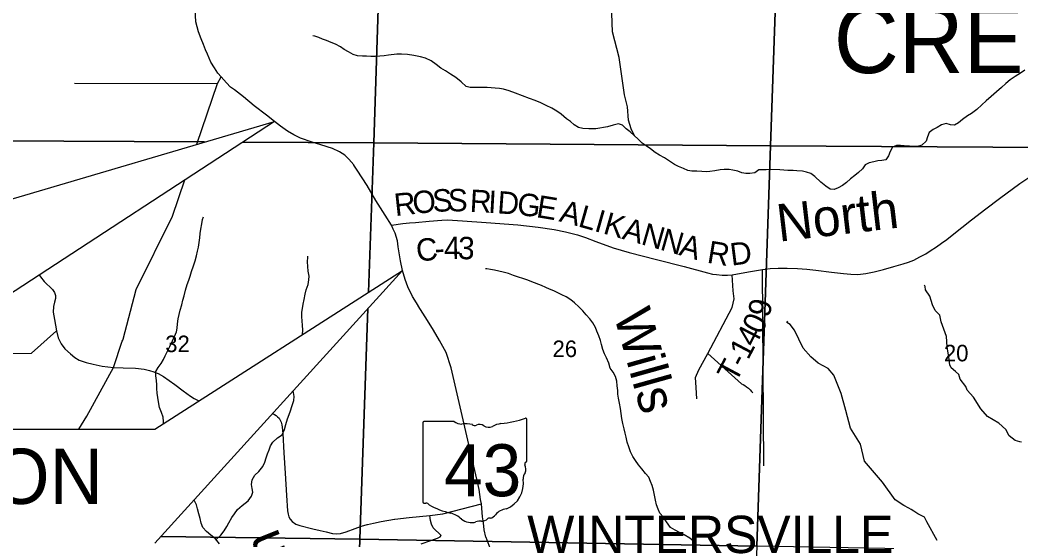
# Model space of a CAD drawing. Extents: x -19 to 40.8, y -1.8 to 26.1.
# Drawn here: x 4.466 to 7.005, y 16.956 to 18.273 of the extents above; entities that cross this region are included whole.
import ezdxf

# ---------------------------------------------------------------- set-up
doc = ezdxf.new("R2010")
doc.units = 0
for name, color, linetype in [('GM_X_Corporation', 7, 'Continuous'), ('GM_X_County_Road_Text', 7, 'Continuous'), ('GM_X_Major_River_Text', 7, 'Continuous'), ('GM_X_Minor_River', 7, 'Continuous'), ('GM_X_Rail_Line', 7, 'Continuous'), ('GM_X_Section', 7, 'Continuous'), ('GM_X_Section_Text', 7, 'Continuous'), ('GM_X_State_Location', 7, 'Continuous'), ('GM_X_State_Route', 7, 'Continuous'), ('GM_X_Township_Road_Text', 7, 'Continuous'), ('GM_X_Township_Text', 7, 'Continuous'), ('GM_X_Unincorporated_Text', 7, 'Continuous'), ('RW_P_Text', 7, 'Continuous'), ('SH_Text', 7, 'Continuous')]:
    doc.layers.add(name, color=color, linetype=linetype)

msp = doc.modelspace()

# ---------------------------------------------------------------- linework, layer by layer
at = {"layer": 'GM_X_Corporation'}
for points in [[(5.4077, 17.7534), (5.4363, 17.7577), (5.4536, 17.7598), (5.469, 17.7606), (5.5039, 17.7635), (5.5357, 17.766), (5.5498, 17.7669), (5.588, 17.7648), (5.6479, 17.76), (5.7282, 17.7541), (5.7803, 17.7488), (5.8207, 17.7427), (5.8495, 17.7367), (5.8797, 17.7287), (5.8999, 17.722), (5.9264, 17.7118), (5.9705, 17.696), (6.0105, 17.6847), (6.0805, 17.6669), (6.1507, 17.6486), (6.2097, 17.6327), (6.2223, 17.6298), (6.2326, 17.6284), (6.2468, 17.627), (6.2606, 17.6265), (6.2721, 17.6278), (6.3134, 17.6356), (6.3494, 17.6416), (6.3689, 17.6436), (6.3892, 17.6444), (6.4115, 17.6445), (6.4383, 17.6439), (6.4619, 17.642), (6.4842, 17.6394), (6.5242, 17.6341), (6.5547, 17.6307), (6.5734, 17.6291), (6.5908, 17.6288), (6.6109, 17.6309), (6.6324, 17.6354), (6.6558, 17.6411), (6.6826, 17.6486), (6.7063, 17.6554), (6.7198, 17.6598), (6.7329, 17.6652), (6.7485, 17.6729), (6.7635, 17.6813), (6.7748, 17.6883), (6.7906, 17.6986), (6.8032, 17.7077), (6.8169, 17.7176), (6.8304, 17.7285), (6.8791, 17.767), (6.9155, 17.7949), (6.9507, 17.8215), (7.002, 17.8591), (7.0427, 17.8858)], [(5.5195, 16.9585), (5.525, 16.9603), (5.5316, 16.9634), (5.5342, 16.9671), (5.5137, 16.9866), (5.5092, 16.9958), (5.5067, 17.0054), (5.5052, 17.0174)], [(5.483, 16.9459), (5.5075, 16.9546), (5.5195, 16.9585)]]:
    msp.add_lwpolyline(points, dxfattribs=at)
at = {"layer": 'GM_X_Rail_Line'}
for points in [[(5.3125, 17.9058), (5.312, 17.9066), (5.2998, 17.921), (5.2894, 17.9307), (5.2757, 17.9394), (5.2586, 17.9477), (5.2285, 17.9575), (5.2069, 17.9639), (5.1769, 17.9744), (5.1605, 17.9825), (5.1443, 17.9922), (5.1266, 18.0046), (5.1108, 18.0166), (5.0907, 18.0322), (5.0594, 18.0564), (5.0326, 18.0785), (5.0093, 18.0968), (4.9999, 18.1037), (4.9891, 18.1139), (4.9755, 18.1295), (4.9674, 18.1388), (4.9589, 18.1522), (4.95, 18.1671), (4.9408, 18.1872), (4.9365, 18.1979), (4.9309, 18.2115), (4.9248, 18.226), (4.9181, 18.2436), (4.9146, 18.2562), (4.9116, 18.2692), (4.9099, 18.3009)], [(5.4754, 17.5499), (5.4613, 17.5724), (5.4496, 17.597), (5.4424, 17.6161), (5.4357, 17.6388), (5.4305, 17.6634), (5.4252, 17.6987), (5.4229, 17.7135), (5.4172, 17.7334), (5.4121, 17.7435), (5.4077, 17.7534), (5.3918, 17.7785), (5.3686, 17.8164), (5.3459, 17.854), (5.3211, 17.8926), (5.3125, 17.9058)], [(4.5141, 17.6275), (4.5179, 17.6223), (4.5271, 17.6104), (4.5481, 17.5902), (4.5529, 17.5825), (4.5552, 17.5757), (4.5557, 17.5677), (4.5534, 17.5588), (4.5501, 17.5475), (4.5494, 17.5333), (4.5534, 17.5144), (4.558, 17.4856), (4.5623, 17.4681), (4.5699, 17.4532), (4.5795, 17.4403), (4.5934, 17.4274), (4.6047, 17.4181), (4.6153, 17.4115), (4.6335, 17.4058), (4.6514, 17.4009), (4.6739, 17.3966), (4.7027, 17.3929), (4.7269, 17.3922), (4.7581, 17.3909), (4.7805, 17.3886), (4.7939, 17.3855), (4.8051, 17.382), (4.811, 17.3796)], [(5.636, 17.0471), (5.634, 17.0581), (5.6305, 17.0839), (5.6245, 17.1099), (5.5594, 17.3923), (5.5464, 17.4309), (5.5299, 17.461), (5.5149, 17.4875), (5.4992, 17.5121), (5.476, 17.5491), (5.4754, 17.5499)], [(4.811, 17.3796), (4.816, 17.3776), (4.8299, 17.3699), (4.8442, 17.36), (4.858, 17.3496), (4.8794, 17.3339), (4.8979, 17.3204), (4.9075, 17.3139), (4.9178, 17.3094), (4.92, 17.3087)], [(5.1061, 17.2762), (5.111, 17.2737), (5.1155, 17.2708), (5.119, 17.268), (5.1226, 17.2642), (5.1259, 17.2596), (5.128, 17.2546), (5.13, 17.2479), (5.1308, 17.2416), (5.1319, 17.2259), (5.1345, 17.1762), (5.1378, 17.1248), (5.1415, 17.0681), (5.1438, 17.0295), (5.1456, 17.0214), (5.1476, 17.0147), (5.1508, 17.0082), (5.1557, 17.0023), (5.1655, 16.9959), (5.1755, 16.992), (5.208, 16.984), (5.2273, 16.9796), (5.2422, 16.9761), (5.2583, 16.9717), (5.2677, 16.9715), (5.2787, 16.9723), (5.293, 16.9761), (5.3158, 16.9851), (5.3315, 16.9906), (5.3464, 16.9948), (5.3474, 16.9951)], [(5.4155, 17.0085), (5.4165, 17.0087), (5.4528, 17.0125), (5.5052, 17.0174), (5.5383, 17.0218), (5.636, 17.0471)], [(5.6478, 16.9623), (5.6474, 16.9632), (5.6431, 16.9811), (5.6411, 16.9989), (5.6392, 17.0147), (5.636, 17.0471)], [(5.3474, 16.9951), (5.3627, 16.9985), (5.3814, 17.0022), (5.4155, 17.0085)], [(5.7631, 16.7982), (5.7251, 16.8529), (5.6987, 16.8841), (5.6791, 16.903), (5.6671, 16.918), (5.6582, 16.9352), (5.6478, 16.9623)]]:
    msp.add_lwpolyline(points, dxfattribs=at)
at = {"layer": 'GM_X_Section'}
for points in [[(6.0242, 17.98), (6.0157, 17.998), (6.0089, 18.0195), (6.0068, 18.0533), (5.9994, 18.084), (5.9853, 18.1788), (5.969, 18.2435), (5.967, 18.2899), (5.9628, 18.3157), (5.9531, 18.3752), (5.9494, 18.3915), (5.9466, 18.3975), (5.9447, 18.4016), (5.946, 18.4104)], [(5.8933, 17.9985), (5.8826, 18.0012), (5.8717, 18.0081), (5.862, 18.0162), (5.8523, 18.0234), (5.8382, 18.0348), (5.8273, 18.0428), (5.8145, 18.05), (5.8006, 18.0572), (5.7864, 18.064), (5.7725, 18.0692), (5.7583, 18.0749), (5.7406, 18.0815), (5.7225, 18.0878), (5.7063, 18.0941), (5.6921, 18.0983), (5.6822, 18.1002), (5.6711, 18.101), (5.6605, 18.1014), (5.6506, 18.1023), (5.6392, 18.1023), (5.627, 18.1027), (5.6072, 18.1021), (5.5976, 18.1052), (5.5847, 18.1169), (5.5714, 18.1275), (5.5579, 18.1362), (5.5447, 18.1446), (5.5327, 18.1518), (5.5217, 18.161), (5.5085, 18.1701), (5.4946, 18.1765), (5.4812, 18.1806), (5.4647, 18.1839), (5.4483, 18.186), (5.4335, 18.1871), (5.4213, 18.1871), (5.4001, 18.1841), (5.3891, 18.1827), (5.3785, 18.1816), (5.3664, 18.1812), (5.3557, 18.1812), (5.3443, 18.1816), (5.3344, 18.1817), (5.3215, 18.1824), (5.3103, 18.1863), (5.2987, 18.1927), (5.2882, 18.1992), (5.2785, 18.2058), (5.2658, 18.2126), (5.255, 18.2165), (5.2427, 18.2214), (5.2331, 18.2253), (5.2234, 18.2288), (5.2134, 18.2323), (5.2081, 18.2336)], [(7.0149, 18.1463), (7.0033, 18.1388), (6.9903, 18.13)], [(6.9903, 18.13), (6.9772, 18.1216), (6.9661, 18.1129), (6.9554, 18.1026), (6.9424, 18.0916), (6.9295, 18.0798), (6.9165, 18.0687), (6.9058, 18.0585), (6.8929, 18.0471), (6.8791, 18.0367), (6.8691, 18.0303), (6.8564, 18.0216), (6.8464, 18.0133), (6.836, 18.0072), (6.8257, 18.0077), (6.8149, 18.0111), (6.8036, 18.0078), (6.7924, 18.0009), (6.782, 17.9957), (6.7723, 17.9885), (6.7677, 17.9773), (6.7642, 17.9662), (6.7531, 17.9567), (6.7422, 17.953), (6.7327, 17.9527), (6.7217, 17.9535), (6.7087, 17.9546), (6.6992, 17.9554), (6.6889, 17.9559), (6.6788, 17.9514), (6.673, 17.9405), (6.6685, 17.9294), (6.6619, 17.9193), (6.6521, 17.9174), (6.6419, 17.9163), (6.6313, 17.9141), (6.6196, 17.9115), (6.6099, 17.9062), (6.6026, 17.8965), (6.593, 17.8871), (6.5833, 17.8795), (6.5726, 17.8712), (6.5622, 17.8617), (6.5518, 17.8538), (6.541, 17.8482), (6.5308, 17.8437), (6.5209, 17.8452), (6.51, 17.8525), (6.4972, 17.8627), (6.4823, 17.8771), (6.4714, 17.8844), (6.461, 17.8882), (6.4503, 17.8906), (6.4366, 17.8909), (6.4271, 17.8917), (6.4134, 17.8924), (6.4034, 17.8933), (6.3935, 17.8937), (6.3684, 17.8944), (6.3586, 17.8941), (6.349, 17.8942), (6.3396, 17.8935), (6.3295, 17.8864), (6.3174, 17.8848), (6.3072, 17.8841), (6.2968, 17.8861), (6.2864, 17.8903), (6.2742, 17.893), (6.2642, 17.8946), (6.2521, 17.8946), (6.2415, 17.8935), (6.2282, 17.8912), (6.2157, 17.8893), (6.2059, 17.8889), (6.1956, 17.8894), (6.1823, 17.8901), (6.1701, 17.8905), (6.1598, 17.8921), (6.1486, 17.8974), (6.1363, 17.9023), (6.1262, 17.9077), (6.1157, 17.9142), (6.1006, 17.924), (6.0878, 17.9312), (6.0766, 17.9381), (6.0653, 17.9469), (6.0544, 17.9545), (6.0439, 17.9618), (6.0337, 17.9714), (6.0235, 17.9805), (6.0134, 17.9901), (6.0029, 17.9978), (5.9942, 18.0074), (5.9842, 18.0101), (5.9703, 18.0066), (5.9559, 18.0031), (5.9461, 18.0009), (5.9363, 17.9991), (5.9264, 17.998), (5.9086, 17.9975), (5.8933, 17.9985)], [(4.9059, 17.6503), (4.91, 17.6634), (4.9134, 17.676), (4.9161, 17.6879), (4.9181, 17.6982), (4.92, 17.7097), (4.9215, 17.7211), (4.9227, 17.7322), (4.9242, 17.7437), (4.9265, 17.757), (4.9288, 17.7681), (4.9313, 17.7743)], [(5.1821, 17.4765), (5.1828, 17.4872), (5.1824, 17.5001), (5.1814, 17.5099), (5.1806, 17.5224), (5.1807, 17.532), (5.1838, 17.5533), (5.1861, 17.5656), (5.1887, 17.5786), (5.1918, 17.5897), (5.1963, 17.6035), (5.1986, 17.615), (5.1987, 17.6245), (5.1968, 17.6366), (5.1956, 17.6492), (5.1949, 17.6609), (5.1953, 17.6723), (5.1956, 17.6746)], [(4.8295, 17.2507), (4.8297, 17.2563), (4.8286, 17.2669), (4.8244, 17.2789), (4.8191, 17.2917), (4.8167, 17.3057), (4.8152, 17.3167), (4.8137, 17.328), (4.813, 17.3398), (4.8123, 17.3493), (4.8116, 17.3599), (4.8105, 17.3713), (4.8101, 17.383), (4.8163, 17.3931), (4.8235, 17.4028), (4.8297, 17.4129), (4.834, 17.4226), (4.8397, 17.4342), (4.8454, 17.4461), (4.8521, 17.4608), (4.8575, 17.4716), (4.8628, 17.4832), (4.8641, 17.4927), (4.8653, 17.5034), (4.8671, 17.516), (4.8694, 17.5275), (4.8721, 17.5382), (4.8759, 17.5516), (4.879, 17.5635), (4.8816, 17.5746), (4.8854, 17.5888), (4.8895, 17.603), (4.8937, 17.6138), (4.8976, 17.6242), (4.901, 17.6365), (4.9059, 17.6503)], [(5.9444, 17.4385), (5.9409, 17.4509), (5.9379, 17.4615), (5.9342, 17.4732), (5.9292, 17.4848), (5.9251, 17.4945), (5.9191, 17.5058), (5.9111, 17.5158), (5.9021, 17.5261), (5.893, 17.5365), (5.8832, 17.5468), (5.8726, 17.5568), (5.8625, 17.5644), (5.8508, 17.5717), (5.84, 17.577), (5.8296, 17.5824), (5.8199, 17.5874), (5.8092, 17.5917), (5.7995, 17.5955), (5.7883, 17.6005), (5.7637, 17.6096), (5.7537, 17.6139), (5.741, 17.6184), (5.7299, 17.6219), (5.7176, 17.6264), (5.7045, 17.6309), (5.6911, 17.6347), (5.6804, 17.6374), (5.6689, 17.6393), (5.6593, 17.6413), (5.6494, 17.6425), (5.6463, 17.6428)], [(7.0059, 17.2034), (7.0017, 17.2041), (6.9899, 17.2077), (6.9746, 17.22), (6.9668, 17.2355), (6.9483, 17.2519), (6.9201, 17.2689), (6.9031, 17.2884), (6.8848, 17.3173), (6.8686, 17.3353), (6.8654, 17.3444), (6.8503, 17.3635), (6.8471, 17.3752), (6.8386, 17.3831), (6.8275, 17.392), (6.8244, 17.3996), (6.8217, 17.4189), (6.8179, 17.4454), (6.8159, 17.4716), (6.8028, 17.5083), (6.7991, 17.5253), (6.7871, 17.5377), (6.7808, 17.5516), (6.7733, 17.5735), (6.7631, 17.5901), (6.7615, 17.598), (6.7599, 17.6014)], [(6.7919, 16.954), (6.7661, 17.0014), (6.7602, 17.0139), (6.743, 17.0223), (6.7334, 17.029), (6.7262, 17.0331), (6.7201, 17.036), (6.7075, 17.0427), (6.6857, 17.0571), (6.6535, 17.1022), (6.6079, 17.1558), (6.5977, 17.1982), (6.5721, 17.2388), (6.5603, 17.2838), (6.5489, 17.3273), (6.53, 17.3734), (6.5157, 17.3899), (6.4901, 17.4035), (6.4721, 17.4199), (6.4524, 17.442), (6.4304, 17.4876), (6.4196, 17.5015), (6.4108, 17.5067), (6.4137, 17.5105)], [(6.1748, 16.9522), (6.1647, 16.9607), (6.1504, 16.969), (6.1384, 16.975), (6.1272, 16.9804), (6.1156, 16.9873), (6.1052, 17.0018), (6.098, 17.0133), (6.0886, 17.024), (6.0841, 17.0338), (6.0803, 17.0451), (6.0776, 17.0568), (6.0754, 17.0693), (6.073, 17.0821), (6.0689, 17.0934), (6.0647, 17.1043), (6.0606, 17.1148), (6.0523, 17.1244), (6.0428, 17.1363), (6.0349, 17.1463), (6.027, 17.1575), (6.0202, 17.1675), (6.0141, 17.1791), (6.0099, 17.1919), (6.0061, 17.204), (6.0031, 17.2164), (6.0005, 17.2266), (5.9978, 17.2375), (5.9947, 17.2511), (5.9921, 17.2636), (5.9902, 17.2761), (5.9886, 17.2886), (5.9863, 17.3026), (5.984, 17.315), (5.9825, 17.3253), (5.9818, 17.3347), (5.9807, 17.3465), (5.9792, 17.3582), (5.9765, 17.3703), (5.9705, 17.3812), (5.963, 17.3912), (5.9595, 17.4036), (5.953, 17.4171), (5.9481, 17.4276), (5.9444, 17.4385)], [(4.9629, 16.9565), (4.9752, 16.9677), (4.9836, 16.9786), (4.9901, 16.9895), (4.9955, 16.9991), (5.0031, 17.0123), (5.0093, 17.022), (5.0173, 17.0333), (5.0287, 17.0435), (5.044, 17.055), (5.0531, 17.0664), (5.0558, 17.0767), (5.0548, 17.0862), (5.0529, 17.0964), (5.0548, 17.1082), (5.0613, 17.1198), (5.0713, 17.1293), (5.0815, 17.1422), (5.0865, 17.153), (5.09, 17.1637), (5.0931, 17.1741), (5.0973, 17.1845), (5.1012, 17.1941), (5.1066, 17.2038), (5.1188, 17.2144), (5.1307, 17.222), (5.1364, 17.2355), (5.1398, 17.2482), (5.1443, 17.2631), (5.1505, 17.2808), (5.1561, 17.2966), (5.1599, 17.3096), (5.1611, 17.3196), (5.1597, 17.3298), (5.1584, 17.3337)], [(4.9717, 16.9463), (4.9615, 16.9582), (4.9497, 16.9681), (4.9384, 16.9772), (4.929, 16.9875), (4.9252, 16.9985), (4.9226, 17.0102), (4.9195, 17.0222), (4.9161, 17.0343), (4.9131, 17.0445), (4.9083, 17.0546), (4.9057, 17.0558)]]:
    msp.add_lwpolyline(points, dxfattribs=at)
at = {"layer": 'GM_X_State_Route'}
for p, q in [((4.6035, 18.1133), (4.9667, 18.1125)), ((6.3523, 17.1436), (6.3494, 17.6416))]:
    msp.add_line(p, q, dxfattribs=at)
for points in [[(4.9145, 17.9588), (4.9667, 18.1125), (4.9755, 18.1295)], [(4.7269, 17.4646), (4.7605, 17.5908), (4.8526, 17.7764), (4.8839, 17.8686)], [(6.1828, 17.3138), (6.1805, 17.3419), (6.1789, 17.3676), (6.1875, 17.3871), (6.2101, 17.4284), (6.2724, 17.5453), (6.2771, 17.5671), (6.2748, 17.5874), (6.2721, 17.6278)], [(4.4107, 17.4287), (4.4946, 17.4289), (4.558, 17.4856)], [(4.7027, 17.3929), (4.7251, 17.4592), (4.7262, 17.4618), (4.7269, 17.4646)], [(6.2101, 17.4284), (6.2958, 17.3517), (6.2998, 17.3496), (6.3044, 17.3468), (6.3088, 17.3437), (6.3133, 17.3401), (6.3176, 17.3361), (6.3211, 17.3324), (6.3246, 17.3283)], [(4.6145, 17.2367), (4.6349, 17.2694), (4.7027, 17.3929)]]:
    msp.add_lwpolyline(points, dxfattribs=at)
at = {"layer": 'GM_X_Unincorporated_Text'}
for p, q in [((5.4874, 17.2525), (5.4874, 17.0523)), ((5.5672, 17.2559), (5.49, 17.2559)), ((5.7511, 17.1562), (5.7511, 17.2609)), ((5.7511, 17.1562), (5.7511, 17.1562))]:
    msp.add_line(p, q, dxfattribs=at)
for centre, radius, start, end in [((5.4905, 17.2529), 0.00305, 98.1301, 188.1301), ((5.5856, 17.2791), 0.0296, 231.6195, 271.1119), ((5.5955, 17.1436), 0.1064, 80.4867, 94.9883), ((5.6196, 17.2539), 0.00855, 219.7921, 297.1024), ((5.6322, 17.2308), 0.0178, 54.4667, 119.1411), ((5.6551, 17.2625), 0.0214, 233.8562, 294.8282), ((5.6928, 17.1948), 0.0563, 97.3462, 120.7689), ((5.6572, 17.5287), 0.2796, 275.8445, 288.9065), ((5.7482, 17.2613), 0.00294, 351.8621, 97.738), ((5.7504, 17.1485), 0.00454, 107.944, 210.337), ((5.7215, 17.1353), 0.0273, 340.033, 23.6496), ((5.748, 17.1558), 0.00314, 289.6038, 7.7341), ((5.7616, 17.1124), 0.0198, 136.8065, 186.9296), ((5.6728, 17.0991), 0.0699, 292.3089, 8.9858), ((5.4905, 17.0519), 0.00308, 171.9584, 258.3066), ((5.491, 17.0724), 0.0235, 267.339, 280.6039), ((5.4958, 17.0408), 0.00848, 29.7484, 93.2717), ((5.6028, 17.2206), 0.2019, 240.4129, 257.1985), ((5.5426, 16.9624), 0.0632, 47.1842, 75.836), ((5.6538, 17.033), 0.0226, 282.8732, 323.2771), ((5.7023, 16.9962), 0.0383, 94.4031, 142.5768), ((5.611, 17.0398), 0.0401, 230.7004, 286.2918), ((5.6341, 16.9706), 0.0329, 85.6951, 111.2099), ((5.637, 17.0248), 0.0214, 268.777, 315.5493), ((5.6564, 17.0054), 0.00601, 65.7517, 132.6484)]:
    msp.add_arc(centre, radius, start, end, dxfattribs=at)
at = {"layer": 'RW_P_Text'}
for points in [[(4.9335, 17.9644), (4.397, 17.9674), (4.4081, 18.8788), (4.411, 18.9653), (5.3949, 18.9546), (5.3629, 17.962), (5.0299, 17.9638)], [(4.3939, 17.8104), (4.395, 17.8752), (4.397, 17.9674), (4.9335, 17.9644)], [(5.0299, 17.9638), (5.3629, 17.962), (5.3496, 17.5837)], [(5.3496, 17.5837), (5.3629, 17.962), (6.3691, 17.9545), (6.3345, 16.9403), (5.3277, 16.9579), (5.3482, 17.5425)], [(5.3482, 17.5425), (5.3277, 16.9579), (4.8227, 16.9645)], [(4.8227, 16.9645), (5.3277, 16.9579), (5.2973, 15.9612), (5.2848, 15.9609), (4.3678, 15.9788), (4.3772, 16.7589)]]:
    msp.add_lwpolyline(points, dxfattribs=at)
for points in [[(5.3949, 18.9546), (6.4041, 18.9461), (6.3691, 17.9545), (5.3629, 17.962)], [(6.4041, 18.9461), (7.3987, 18.9308), (7.3559, 17.9489), (6.3691, 17.9545)], [(6.3691, 17.9545), (7.3559, 17.9489), (7.309, 16.9219), (6.3345, 16.9403)], [(6.3345, 16.9403), (6.2953, 15.9429), (5.2973, 15.9612), (5.3277, 16.9579)]]:
    msp.add_lwpolyline(points, close=True, dxfattribs=at)
at = {"layer": 'SH_Text'}
msp.add_line((2.7742, 17.2367), (4.8076, 17.2367), dxfattribs=at)
for points in [[(4.4107, 17.8104), (5.1108, 18.0166), (4.4107, 17.56)], [(4.8076, 17.2367), (5.4357, 17.6388), (4.8076, 16.9478)]]:
    msp.add_lwpolyline(points, dxfattribs=at)

# ---------------------------------------------------------------- texts
at = {"layer": 'GM_X_County_Road_Text'}
for s, rotation, p in [('R', 6.257, (5.4178, 17.7764)), ('O', 6.0731, (5.4642, 17.7815)), ('S', 3.1804, (5.5131, 17.7867)), ('S', 359.4346, (5.5504, 17.7888)), ('R', 356.794, (5.6055, 17.7876)), ('I', 356.7903, (5.6521, 17.785)), ('D', 355.9567, (5.6752, 17.7837)), ('G', 352.7937, (5.7243, 17.7803)), ('E', 350.6765, (5.7733, 17.7741)), ('A', 345.2446, (5.831, 17.7637)), ('L', 344.1788, (5.879, 17.751)), ('I', 344.1775, (5.9199, 17.7394)), ('K', 344.1762, (5.9424, 17.7331)), ('A', 344.1773, (5.9905, 17.7194)), ('N', 344.1797, (6.0386, 17.7058)), ('3', 357.8762, (5.5757, 17.668)), ('N', 344.1762, (6.0867, 17.6922)), ('A', 344.1846, (6.1348, 17.6785)), ('C', 5.7549, (5.4731, 17.661)), ('4', 1.2074, (5.5416, 17.6672)), ('R', 350.5919, (6.2065, 17.6587)), ('D', 7.2488, (6.2706, 17.6508)), ('-', 3.8826, (5.519, 17.6657))]:
    msp.add_text(s, height=0.0568, rotation=rotation, dxfattribs=at).set_placement(p)
at = {"layer": 'GM_X_Major_River_Text'}
msp.add_text('WINTERSVILLE', height=0.094697, rotation=0, dxfattribs=at).set_placement((5.7523, 16.9225))
at = {"layer": 'GM_X_Minor_River'}
for s, height, rotation, p in [('North', 0.09471, 6.7071, (6.3908, 17.7115)), ('Wills', 0.09467, 285.6526, (5.9711, 17.5271)), ('Run', 0.09467, 111.8301, (5.2032, 16.7735))]:
    msp.add_text(s, height=height, rotation=rotation, dxfattribs=at).set_placement(p)
at = {"layer": 'GM_X_Section_Text'}
for s, p in [('32', (4.834, 17.4318)), ('26', (5.8165, 17.4193)), ('20', (6.8094, 17.4084))]:
    msp.add_text(s, height=0.04186, rotation=0, dxfattribs=at).set_placement(p)
at = {"layer": 'GM_X_State_Location'}
msp.add_text('43', height=0.000189, rotation=0, dxfattribs=at).set_placement((5.5686, 17.1253))
for s in ['s', 'r']:
    msp.add_text(s, height=0.000189, dxfattribs=at).set_placement((5.6163, 17.1391))
at = {"layer": 'GM_X_Township_Road_Text'}
for s, rotation, p in [('9', 75.8528, (6.3657, 17.5175)), ('0', 64.0846, (6.346, 17.4741)), ('4', 62.612, (6.3292, 17.4416)), ('1', 62.0795, (6.3125, 17.4102)), ('-', 61.9157, (6.3015, 17.3894)), ('T', 61.892, (6.2814, 17.3519))]:
    msp.add_text(s, height=0.0568, rotation=rotation, dxfattribs=at).set_placement(p)
at = {"layer": 'GM_X_Township_Text'}
msp.add_text('CREEK', height=0.17045, rotation=0, dxfattribs=at).set_placement((6.5302, 18.139))
at = {"layer": 'GM_X_Unincorporated_Text'}
msp.add_text('43', height=0.13184, dxfattribs=at).set_placement((5.5411, 17.0665))
at = {"layer": 'SH_Text'}
msp.add_text('BEGIN ACQUISITION', height=0.14, dxfattribs=at).set_placement((2.8242, 17.0471))

doc.saveas('drawing.dxf')
